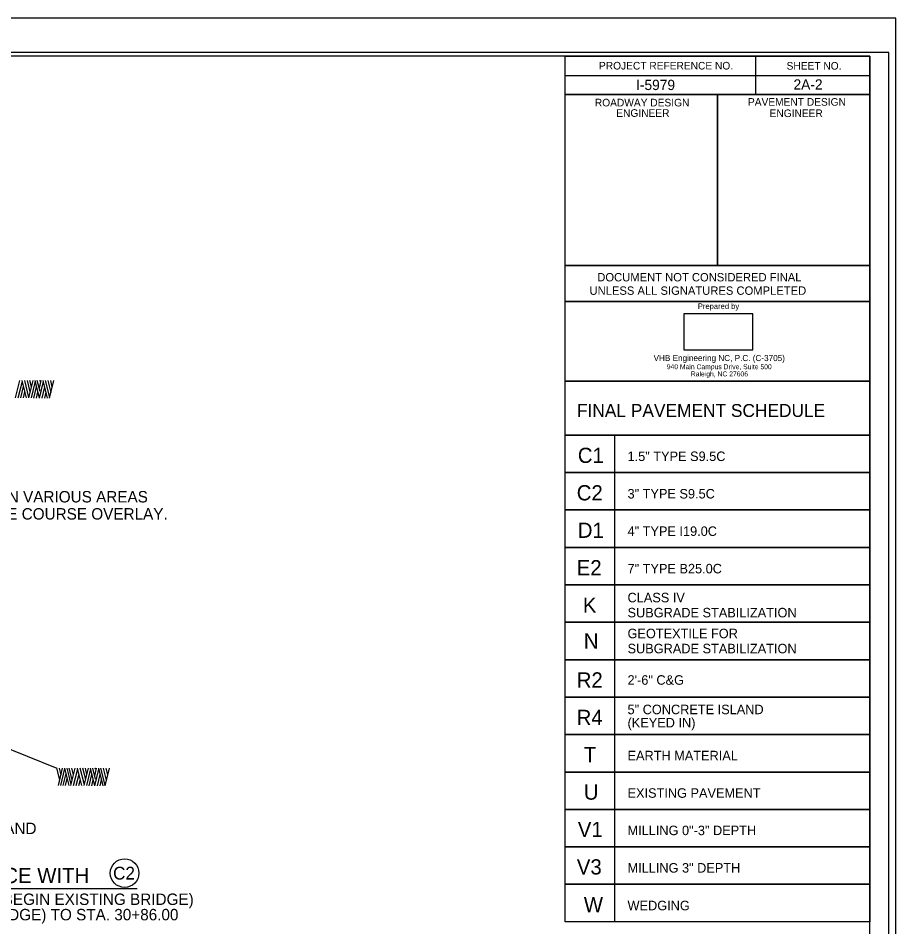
# Model space of a CAD drawing. Extents: x 573748 to 574632, y -54663 to -53209.
# Drawn here: x 574165.8 to 574281, y -53563.1 to -53443.7 of the extents above; entities that cross this region are included whole.
import ezdxf

# ---------------------------------------------------------------- set-up
doc = ezdxf.new("R2010")
doc.units = 0
for name, color, linetype in [('Default', 7, 'Continuous'), ('Prop Dimension', 7, 'Continuous'), ('Prop Pavement Schedule Description CELL', 7, 'Continuous'), ('Sheet Cutting Line CELL', 7, 'Continuous'), ('Sheet Data Field CELL', 7, 'Continuous'), ('Sheet Plan CELL', 7, 'Continuous'), ('Sheet Plot Border Inside CELL', 7, 'Continuous'), ('Sheet Plot Border Outside CELL', 7, 'Continuous'), ('Sheet Sticker Exception Certification CELL', 7, 'Continuous'), ('Sheet Typical CELL', 7, 'Continuous'), ('Typical ID Circle CELL', 7, 'Continuous'), ('Typical Slope Point Local CELL', 7, 'Continuous'), ('Typical Text General CELL', 7, 'Continuous'), ('Typical Text ID Circle CELL', 7, 'Continuous')]:
    doc.layers.add(name, color=color, linetype=linetype)

msp = doc.modelspace()

# ---------------------------------------------------------------- linework, layer by layer
at = {"layer": 'Default'}
msp.add_lwpolyline([(574253.15, -53487.27), (574262.18, -53487.27), (574262.18, -53482.55), (574253.15, -53482.55)], close=True, dxfattribs=at)
at = {"layer": 'Prop Dimension'}
for p, q in [((574160.42, -53538.02), (574170.83, -53542.22)), ((574171.21, -53543.77), (574170.83, -53542.22)), ((574171.03, -53544.5), (574171.59, -53542.21)), ((574171.38, -53543.09), (574171.17, -53542.22)), ((574171.33, -53544.5), (574171.88, -53542.29)), ((574172.43, -53544.5), (574171.86, -53542.22)), ((574172.43, -53543.29), (574172.17, -53542.22)), ((574172.85, -53543.75), (574172.46, -53542.22)), ((574172.66, -53544.5), (574173.22, -53542.22)), ((574173.01, -53543.09), (574172.8, -53542.22)), ((574173.03, -53544.5), (574173.57, -53542.33)), ((574174.11, -53544.5), (574173.54, -53542.22)), ((574174.44, -53544.44), (574173.89, -53542.22)), ((574174.61, -53543.73), (574174.24, -53542.22)), ((574174.42, -53544.5), (574174.99, -53542.22)), ((574174.77, -53543.06), (574174.57, -53542.22)), ((574174.76, -53544.5), (574175.3, -53542.33)), ((574175.8, -53544.54), (574175.23, -53542.25)), ((574175.89, -53543.69), (574175.53, -53542.25)), ((574175.8, -53543.22), (574176.04, -53542.25)), ((574175.81, -53544.54), (574176.35, -53542.37)), ((574175.89, -53542.36), (574175.86, -53542.25)), ((574175.93, -53542.33), (574175.9, -53542.22)), ((574176.89, -53544.54), (574176.32, -53542.25)), ((574177.17, -53544.47), (574176.62, -53542.25)), ((574177.33, -53543.81), (574176.95, -53542.25)), ((574177.15, -53544.54), (574177.72, -53542.25)), ((574177.5, -53543.12), (574177.29, -53542.25)), ((574171.66, -53544.5), (574172.04, -53542.95)), ((574171.98, -53544.5), (574172.2, -53543.6)), ((574172.7, -53544.36), (574172.43, -53543.29)), ((574173.37, -53544.5), (574173.74, -53543.02)), ((574173.72, -53544.5), (574173.91, -53543.71)), ((574175.07, -53544.54), (574175.43, -53543.06)), ((574175.82, -53543.09), (574175.8, -53543.01)), ((574176.16, -53544.54), (574176.52, -53543.06)), ((574175.42, -53544.54), (574175.61, -53543.77)), ((574176.52, -53544.54), (574176.7, -53543.77))]:
    msp.add_line(p, q, dxfattribs=at)
at = {"layer": 'Prop Pavement Schedule Description CELL'}
msp.add_lwpolyline([(574237.56, -53491.39), (574277.57, -53491.39), (574277.57, -53498.47), (574237.56, -53498.47)], close=True, dxfattribs=at)
for points in [[(574244.08, -53503.39), (574237.56, -53503.39), (574237.56, -53498.47), (574277.57, -53498.47), (574277.57, -53503.39), (574244.08, -53503.39), (574244.08, -53498.47)], [(574244.08, -53508.31), (574237.56, -53508.31), (574237.56, -53503.39), (574277.57, -53503.39), (574277.57, -53508.31), (574244.08, -53508.31), (574244.08, -53503.39)], [(574244.08, -53513.23), (574237.56, -53513.23), (574237.56, -53508.31), (574277.57, -53508.31), (574277.57, -53513.23), (574244.08, -53513.23), (574244.08, -53508.31)], [(574244.08, -53518.15), (574237.56, -53518.15), (574237.56, -53513.23), (574277.57, -53513.23), (574277.57, -53518.15), (574244.08, -53518.15), (574244.08, -53513.23)], [(574244.08, -53523.06), (574237.56, -53523.06), (574237.56, -53518.15), (574277.57, -53518.15), (574277.57, -53523.06), (574244.08, -53523.06), (574244.08, -53518.15)], [(574244.08, -53527.98), (574237.56, -53527.98), (574237.56, -53523.06), (574277.57, -53523.06), (574277.57, -53527.98), (574244.08, -53527.98), (574244.08, -53523.06)], [(574244.08, -53532.9), (574237.56, -53532.9), (574237.56, -53527.98), (574277.57, -53527.98), (574277.57, -53532.9), (574244.08, -53532.9), (574244.08, -53527.98)], [(574244.08, -53537.82), (574237.56, -53537.82), (574237.56, -53532.9), (574277.57, -53532.9), (574277.57, -53537.82), (574244.08, -53537.82), (574244.08, -53532.9)], [(574244.08, -53542.74), (574237.56, -53542.74), (574237.56, -53537.82), (574277.57, -53537.82), (574277.57, -53542.74), (574244.08, -53542.74), (574244.08, -53537.82)], [(574244.08, -53547.66), (574237.56, -53547.66), (574237.56, -53542.74), (574277.57, -53542.74), (574277.57, -53547.66), (574244.08, -53547.66), (574244.08, -53542.74)], [(574244.08, -53552.57), (574237.56, -53552.57), (574237.56, -53547.66), (574277.57, -53547.66), (574277.57, -53552.57), (574244.08, -53552.57), (574244.08, -53547.66)], [(574244.08, -53557.49), (574237.56, -53557.49), (574237.56, -53552.57), (574277.57, -53552.57), (574277.57, -53557.49), (574244.08, -53557.49), (574244.08, -53552.57)], [(574244.08, -53562.41), (574237.56, -53562.41), (574237.56, -53557.49), (574277.57, -53557.49), (574277.57, -53562.41), (574244.08, -53562.41), (574244.08, -53557.49)]]:
    msp.add_lwpolyline(points, dxfattribs=at)
at = {"layer": 'Sheet Cutting Line CELL'}
msp.add_line((574280.97, -53443.7), (573944.17, -53443.7), dxfattribs=at)
at = {"layer": 'Sheet Plan CELL'}
msp.add_lwpolyline([(574237.56, -53480.91), (574277.57, -53480.91), (574277.57, -53491.39), (574237.56, -53491.39)], close=True, dxfattribs=at)
at = {"layer": 'Sheet Plot Border Inside CELL'}
msp.add_lwpolyline([(574280.07, -53448.19), (573946.77, -53448.19), (573946.77, -53659.21), (574280.07, -53659.21)], close=True, dxfattribs=at)
at = {"layer": 'Sheet Plot Border Outside CELL'}
msp.add_lwpolyline([(574280.97, -53443.7), (573944.17, -53443.7), (573944.17, -53663.7), (574280.97, -53663.7)], close=True, dxfattribs=at)
at = {"layer": 'Sheet Sticker Exception Certification CELL'}
for p, q in [((574237.56, -53480.91), (574237.56, -53476.21)), ((574237.56, -53476.21), (574277.57, -53476.21)), ((574277.57, -53476.21), (574277.57, -53480.91)), ((574277.57, -53480.91), (574237.56, -53480.91))]:
    msp.add_line(p, q, dxfattribs=at)
at = {"layer": 'Sheet Typical CELL'}
for p, q in [((574262.57, -53448.71), (574262.57, -53453.71)), ((574237.56, -53451.21), (574277.57, -53451.21)), ((574257.57, -53453.71), (574257.57, -53476.2))]:
    msp.add_line(p, q, dxfattribs=at)
for points in [[(574277.57, -53448.7), (573977.57, -53448.7), (573977.57, -53658.7), (574277.57, -53658.7)], [(574237.56, -53448.7), (574277.57, -53448.7), (574277.57, -53453.71), (574237.56, -53453.71)], [(574237.56, -53453.71), (574257.57, -53453.71), (574257.57, -53476.21), (574237.56, -53476.21)], [(574257.57, -53453.71), (574277.57, -53453.71), (574277.57, -53476.21), (574257.57, -53476.21)]]:
    msp.add_lwpolyline(points, close=True, dxfattribs=at)
at = {"layer": 'Typical ID Circle CELL'}
msp.add_circle((574179.72, -53556.02), 1.88, dxfattribs=at)
at = {"layer": 'Typical Slope Point Local CELL'}
for p, q in [((574165.39, -53493.57), (574165.96, -53491.29)), ((574165.76, -53493.57), (574166.3, -53491.4)), ((574166.1, -53493.57), (574166.47, -53492.09)), ((574166.84, -53493.57), (574166.27, -53491.29)), ((574167.17, -53493.51), (574166.62, -53491.29)), ((574167.34, -53492.8), (574166.97, -53491.29)), ((574167.16, -53493.57), (574167.72, -53491.29)), ((574167.51, -53492.13), (574167.3, -53491.29)), ((574167.49, -53493.57), (574168.03, -53491.4)), ((574167.8, -53493.61), (574168.16, -53492.13)), ((574168.53, -53493.61), (574167.96, -53491.32)), ((574168.62, -53492.75), (574168.26, -53491.32)), ((574168.53, -53492.29), (574168.77, -53491.32)), ((574168.55, -53492.16), (574168.53, -53492.08)), ((574168.54, -53493.61), (574169.08, -53491.44)), ((574168.62, -53491.43), (574168.59, -53491.32)), ((574168.66, -53491.4), (574168.63, -53491.29)), ((574168.89, -53493.61), (574169.25, -53492.13)), ((574169.62, -53493.61), (574169.05, -53491.32)), ((574169.9, -53493.54), (574169.35, -53491.32)), ((574170.07, -53492.88), (574169.68, -53491.32)), ((574169.88, -53493.61), (574170.45, -53491.32)), ((574170.23, -53492.19), (574170.02, -53491.32)), ((574166.45, -53493.57), (574166.64, -53492.78)), ((574168.16, -53493.61), (574168.34, -53492.84)), ((574169.25, -53493.61), (574169.43, -53492.84))]:
    msp.add_line(p, q, dxfattribs=at)
at = {"layer": 'Typical Text General CELL'}
msp.add_line((574128.71, -53558.02), (574181.37, -53558.02), dxfattribs=at)

# ---------------------------------------------------------------- texts
at = {"layer": 'Default'}
for s, height, rotation, p in [('Prepared by', 0.7214, 360, (574254.98, -53481.9)), ('VHB Engineering NC, P.C. (C-3705)', 0.8, 359.9612, (574249.17, -53488.74)), ('940 Main Campus Drive, Suite 500', 0.6436, 359.9612, (574250.9, -53489.81)), ('Raleigh, NC 27606', 0.6436, 359.9612, (574254.06, -53490.75))]:
    msp.add_text(s, height=height, rotation=rotation, dxfattribs=at).set_placement(p)
at = {"layer": 'Prop Pavement Schedule Description CELL'}
for s, height, p in [('FINAL PAVEMENT SCHEDULE', 1.7, (574239.11, -53496.09)), ('C1', 2, (574239.22, -53502.13)), ('1.5" TYPE S9.5C', 1.25, (574245.75, -53501.88)), ('C2', 2, (574239.08, -53507.05)), ('3" TYPE S9.5C', 1.25, (574245.75, -53506.8)), ('D1', 2, (574239.22, -53511.97)), ('4" TYPE I19.0C', 1.25, (574245.75, -53511.72)), ('E2', 2, (574239.08, -53516.89)), ('7" TYPE B25.0C', 1.25, (574245.75, -53516.64)), ('K', 2, (574239.89, -53521.81)), ('CLASS IV', 1.25, (574245.75, -53520.44)), ('SUBGRADE STABILIZATION', 1.25, (574245.75, -53522.42)), ('N', 2, (574240.01, -53526.52)), ('GEOTEXTILE FOR', 1.25, (574245.75, -53525.16)), ('SUBGRADE STABILIZATION', 1.25, (574245.75, -53527.14)), ('R2', 2, (574239.08, -53531.64)), ('2\'-6" C&G', 1.25, (574245.75, -53531.27)), ('5" CONCRETE ISLAND', 1.25, (574245.75, -53535.14)), ('R4', 2, (574239.07, -53536.56)), ('(KEYED IN)', 1.25, (574245.75, -53536.88)), ('T', 2, (574240.01, -53541.45)), ('EARTH MATERIAL', 1.25, (574245.75, -53541.2)), ('U', 2, (574240.01, -53546.37)), ('EXISTING PAVEMENT', 1.25, (574245.75, -53546.12)), ('V1', 2, (574239.22, -53551.28)), ('MILLING 0"-3" DEPTH', 1.25, (574245.75, -53551.03)), ('V3', 2, (574239.09, -53556.2)), ('MILLING 3" DEPTH', 1.25, (574245.75, -53555.95)), ('W', 2, (574240.01, -53561.15)), ('WEDGING', 1.25, (574245.75, -53560.9))]:
    msp.add_text(s, height=height, dxfattribs=at).set_placement(p)
at = {"layer": 'Sheet Data Field CELL'}
for s, p in [('I-5979', (574246.87, -53453.14)), ('2A-2', (574267.54, -53453.08))]:
    msp.add_text(s, height=1.35, dxfattribs=at).set_placement(p)
at = {"layer": 'Sheet Sticker Exception Certification CELL'}
for s, p in [('DOCUMENT NOT CONSIDERED FINAL', (574241.78, -53478.28)), ('UNLESS ALL SIGNATURES COMPLETED', (574240.76, -53480.04))]:
    msp.add_text(s, height=1.1, dxfattribs=at).set_placement(p)
at = {"layer": 'Sheet Typical CELL'}
for s, p in [('PROJECT REFERENCE NO.', (574242, -53450.44)), ('SHEET NO.', (574266.63, -53450.46)), ('PAVEMENT DESIGN', (574261.56, -53455.2)), ('ROADWAY DESIGN', (574241.46, -53455.29)), ('ENGINEER', (574244.27, -53456.66)), ('ENGINEER', (574264.4, -53456.69))]:
    msp.add_text(s, height=1, dxfattribs=at).set_placement(p)
at = {"layer": 'Typical Text General CELL'}
for s, height, p in [('INCIDENTAL MILLING MAY BE REQUIRED IN VARIOUS AREAS', 1.5, (574123.48, -53507.32)), ('IN ORDER TO FACILITATE THE 3" SURFACE COURSE OVERLAY.', 1.5, (574123.48, -53509.57)), ('SEE PLANS FOR LIMITS OF CONC. ISLAND', 1.5, (574127.03, -53550.89)), ('NOTE: MILL WITH   AND RESURFACE WITH ', 2, (574119.96, -53557.33)), ('-L- STA. 28+00.00 TO STA. 28+38.30 (BEGIN EXISTING BRIDGE)', 1.5, (574128.71, -53560.2)), ('-L- STA. 30+66.70 (END EXISTING BRIDGE) TO STA. 30+86.00', 1.5, (574128.71, -53562.22))]:
    msp.add_text(s, height=height, dxfattribs=at).set_placement(p)
at = {"layer": 'Typical Text ID Circle CELL'}
msp.add_text('C2', height=1.679, dxfattribs=at).set_placement((574178.21, -53556.86))

doc.saveas('drawing.dxf')
